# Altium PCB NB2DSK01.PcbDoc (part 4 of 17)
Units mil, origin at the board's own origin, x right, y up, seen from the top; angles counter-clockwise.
Board outline 11815 x 6500.03 mil, 8 copper layers (Top Layer, MidLayer1, MidLayer2, GND, PWR, MidLayer3, MidLayer4, Bottom Layer), stack 74.62 mil thick; 798 components, 1002 nets, 3927 pads, 3182 vias.
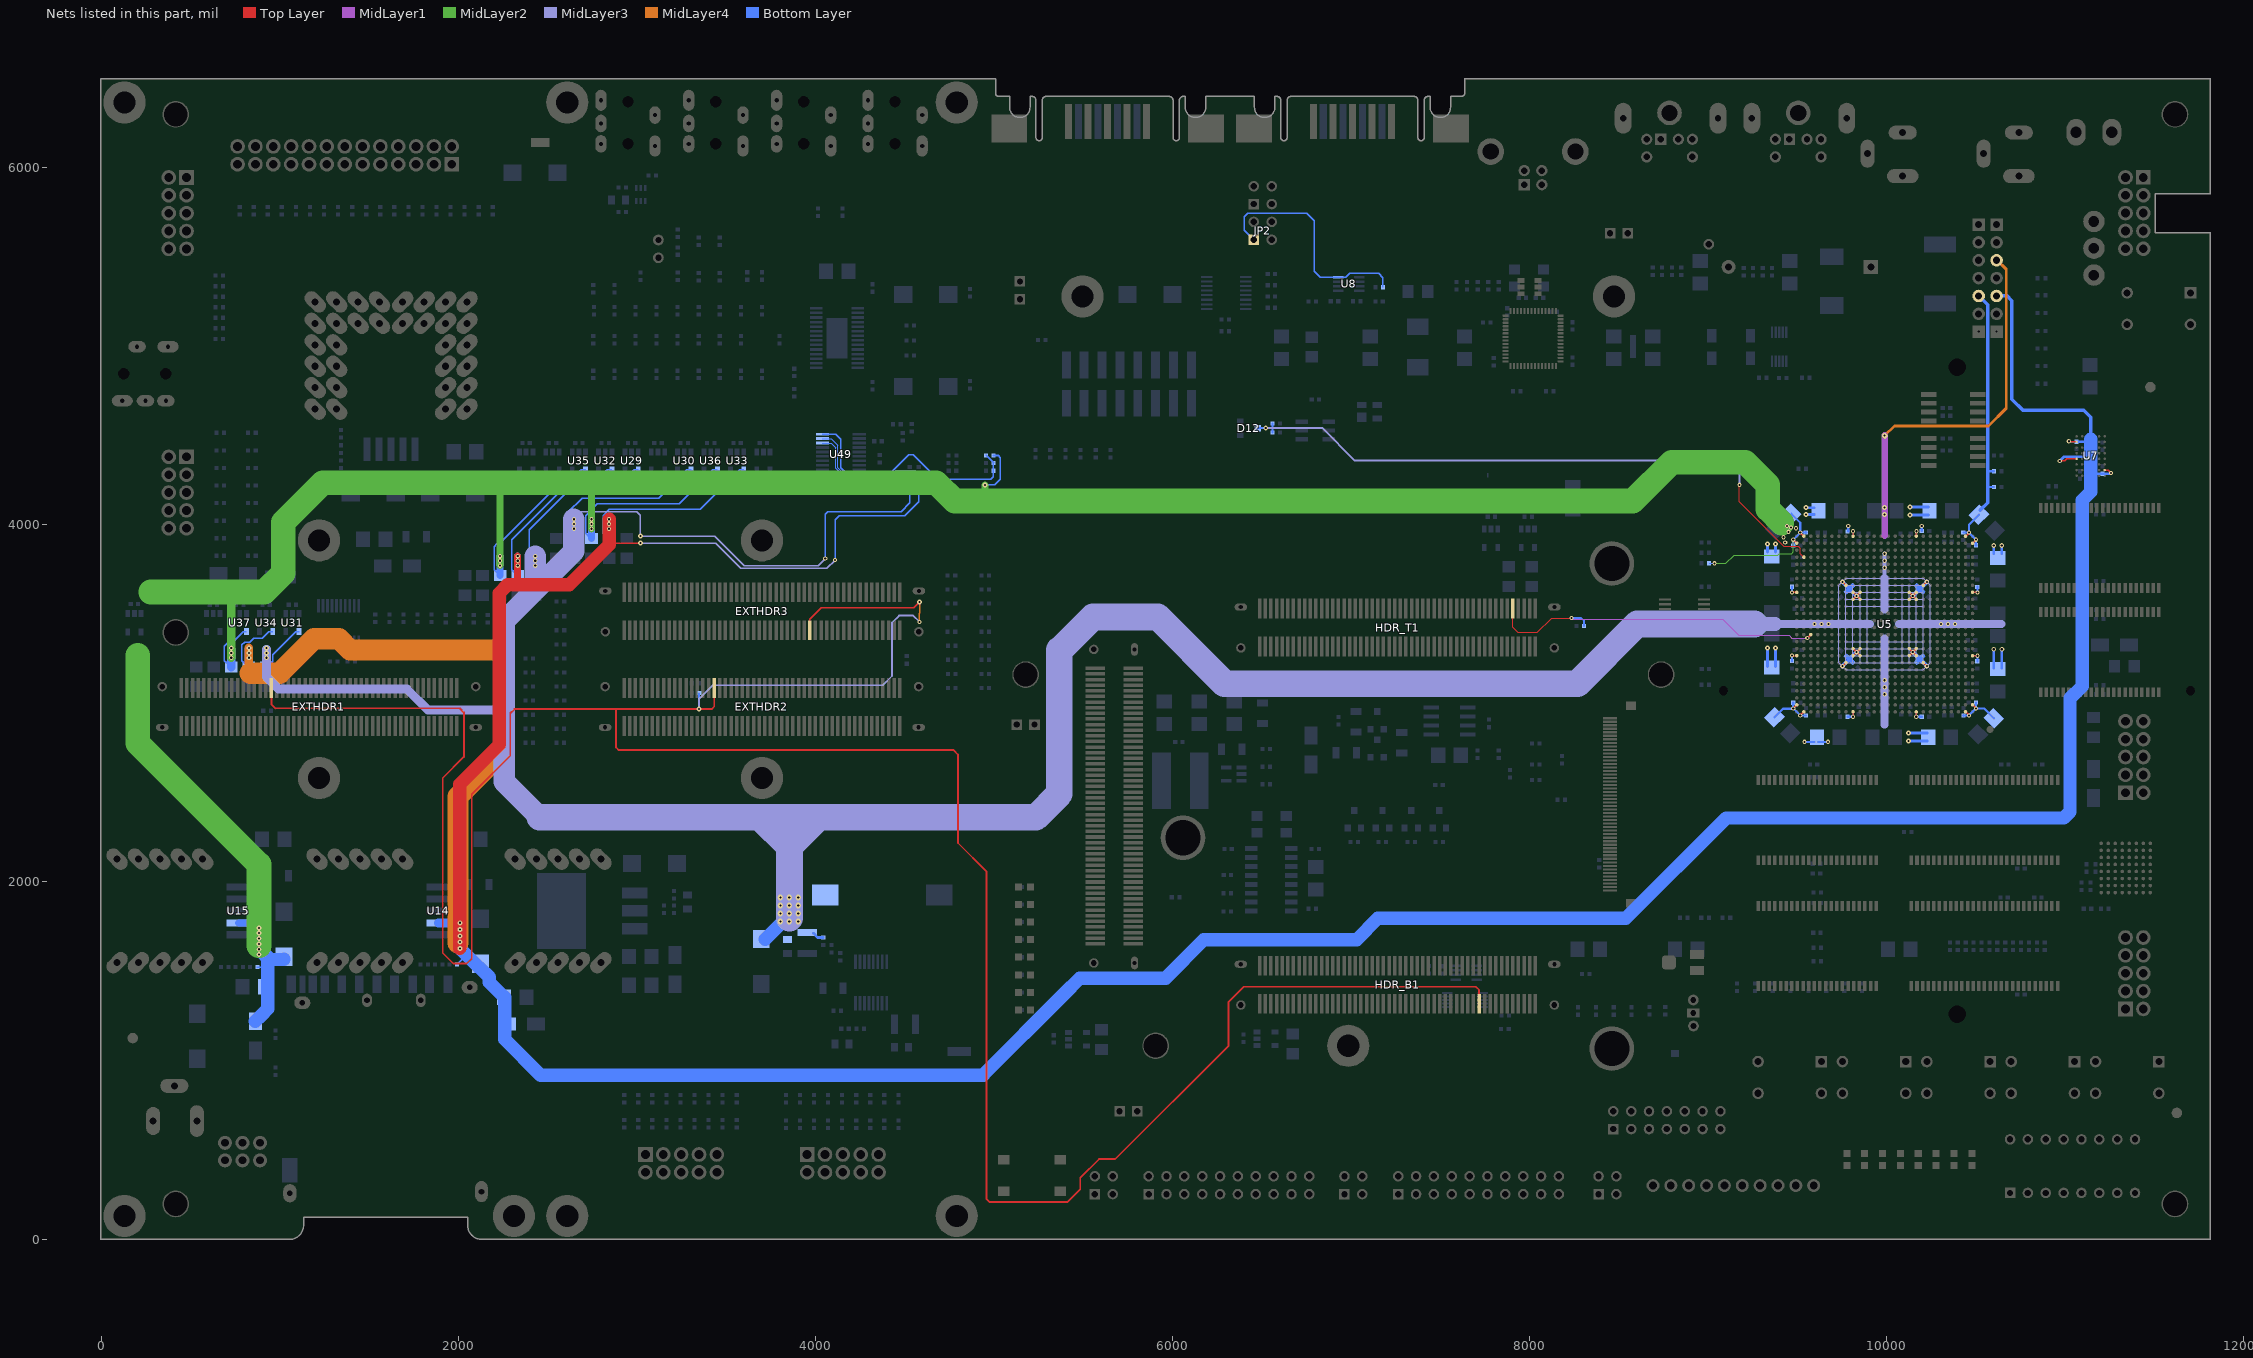
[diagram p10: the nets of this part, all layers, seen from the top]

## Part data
"Altium Logo BOT1" "Altium Logo Top1": library part D-000-0003, "Altium Logo for PCB"
BT1: library part D-302-0000, "Lithium Battery Holder for CR2032 3V Cell"
C1 C2 C3 C4 C137 C150 C160 C164 C168 C177 C180: library part D-101-0088, "Capacitor, Tantalum, 220uF 10% 10V MCCT-D (7343-31)"
C5 C6 C7 C8 C118: library part D-101-0078, "Capacitor, Ceramic, 100pF 5% 50V 0402 (1005) COG"
C9 C11 C14 C17 C26 C27 C28 C29 C38 C39 C40 C41 C42 C58 C59 C60 C61 C62 C63 C64 C65 C66 C67 C68 C69 C70 C71 C72 C73 C74 C75 C76 C77 C78 C79 C80 C81 C82 C83 C84 C115 C117 C119 C120 C121 C122 C125 C126 C127 C129 C134 C141 C153 C154 C155 C156 C174 C194 C195 C196 C198 C200 C202 C203 C204 C205 C206 C211 C212 C216 C219 C220 C221 C222 C227 C228 C229 C230 C235 C236 C237 C238 C239 C240 C241 C242 C243 C244 C245 C246 C247 C248 C249 C250 C251 C252 C253 C254 C255 C256 C257 C258 C259 C260 C261 C262 C263 C264 C265 C267 C268 C272: library part D-101-0080, "Capacitor, Ceramic, 0.1uF 10% 16V 0402 (1005) X7R"
C10 C15 C16 C18 C19 C20 C21 C22 C23 C24 C25 C34 C35 C36 C37 C54 C55 C56 C57 C114 C116 C123 C124 C132 C133 C135 C136 C140 C143 C158 C159 C162 C163 C166 C167 C169 C170 C193 C217 C218 C266 C273: library part D-101-0007, "Capacitor, Tantalum, 10uF 10% 20V MCCT-B (3528)"
C12 C13: library part D-101-0075, "Capacitor, Ceramic, 15pF 5% 50V 0402 (1005)"
C30 C31 C32 C33 C43 C44 C45 C46 C47 C48 C49 C50 C51 C52 C53 C85 C86 C87 C88 C89 C90 C91 C92 C93 C94 C95 C96 C97 C98 C99 C100 C101 C102 C103 C104 C105 C106 C107 C108 C109 C110 C111 C112 C113 C199 C201 C207 C208 C209 C210 C213 C214 C215 C223 C224 C225 C226 C231 C232 C233 C234: library part D-101-0077, "Capacitor, Ceramic, 10nF 10% 16V 0402 (1005) X7R"
C128 C130 C131 C139 C144 C151 C157 C161 C165: library part D-101-0027, "Capacitor, Ceramic, 1uF 10% 25V 1206 (3216) X7R"
C138 C142 C146 C148 C152 C197: library part D-101-0087, "Capacitor, Ceramic, 10uF 10% 10V 0805 (2012) X5R"
C145: library part D-101-0069, "Capacitor, Ceramic, 470pF 5% 50V 0402 (1005) COG"
C147 C149: library part D-101-0021, "Capacitor, Ceramic, 22uF -20%/+80% 10V 1210 (3225) Y5V"
C171 C173 C175 C176 C178 C179 C182 C183 C184 C185 C186 C187 C188 C190 C191 C192: library part D-101-0082, "Capacitor, Ceramic, 1uF 10% 6.3V 0402 (1005) X5R"
C172 C181 C189: library part D-101-0070, "Capacitor, Ceramic, 4.7nF 10% 25V 0402 (1005) X7R"
C269 C270: library part D-101-0059, "Capacitor, Ceramic, 22pF 5% 50V 0402 (1005) COG"
C271: library part D-101-0019, "Capacitor, Ceramic, 4.7nF 20% 250V Panasonic BC J Lead (CAPM7163) Y5V"
D1: library part D-150-0001, "Zener Diode, 5V 5W"
D2: library part D-150-0002, "Zener Diode, 7.5V 35mA"
D3: library part D-151-0001, "Schottky Diode, Dual-Serial, BAT54S 30V 200mA"
D4 D5 D6 D7 D8 D9 D10 D11: library part D-151-0000, "Schottky Diode, 3A 40V"
D12: library part D-150-0005, "Zener Diode, 3.3V"
DH1 DH2 HDR1 HDR2 HDR3: library part D-300-0014, "Header IDC, 2 x 5 Pin Right-Angle 2.54mm Pitch (Boxed-Male)"
EXTHDR1 EXTHDR2 EXTHDR3 HDR_B1 HDR_L1 HDR_T1: library part D-300-0026, "Connector, Molex Docking Station 100 Pin Female 53751"
F1: library part D-106-0002, "Mutifuse, SMD 8A"
F2 F3 F4 F5: library part D-106-0001, "Multifuse, SMD 1206, 350mA"
FD1 FD2 FD3: library part D-004-0001, "Fiducial - Round 1.5mm Top-Bottom"
FP1: library part "Generic No Pins"
GP1 GP2 GP3 GP4: library part D-300-0020, "Header IDC, 2 x 1 Pin Vertical 2.54mm Pitch (Non-Boxed, Male)"
HDR4: library part D-300-0022, "Header IDC, 2 x 5 Pin Right-Angle 2.54mm Pitch (Non-Boxed, Male)"
HDR5: library part D-300-0024, "Header IDC, 2 x 5 Pin Right-Angle 2.54mm Pitch (Non-Boxed, Male)"
HDR6: library part D-300-0015, "Header IDC, 2 x 13 Pin Right-Angle 2.54mm Pitch (Boxed-Male)"
HDR7: library part D-300-0017, "Header IDC, 2 x 7 Pin Vertical 2.54mm Pitch (Non-Boxed, Male)"
J1 J2 J3: library part D-300-0007, "Connector, 3 Conductor Power Jack 2 break 2 aux contacts"
J4: library part D-300-0000, "Connector, USB B Type, Right Angle, Thru Hole, White"
J5: library part D-300-0036, "MINI DIN R/A F/SHLD 6P GOLD PLATED--PURPLE PC99 RoHS Compliant"
J6: library part D-300-0037, "MINI-DIN R/A F/SHLD 6P GOLD PLATED--GREEN PC99 RoHS Compliant"
J7 J9: library part D-300-0060, "Connector DB9 SMD Male/Pins; SUYIN"
J8: library part D-300-0003, "Secure Digital Card Socket"
J10 J14: library part D-300-0033, "Connector, 3.5mm Stereo Audio Socket, Black, 2 break contacts (normals) and 2 auxiliary make contacts"
J11: library part D-300-0030, "Connector, 3.5mm Stereo Audio Socket, Red, 2 break contacts (normals) and 2 auxiliary make contacts"
J12: library part D-300-0031, "Connector, 3.5mm Stereo Audio Socket, Green, 2 break contacts (normals) and 2 auxiliary make contacts"
J13: library part D-300-0032, "Connector, 3.5mm Stereo Audio Socket, Blue, 2 break contacts (normals) and 2 auxiliary make contacts"
J15: library part D-300-0061, "Header, 2x8, 0.1\", Straight, SMT"
JP1 JP2 JP3 JP4 JP5: library part D-300-0019, "Header IDC, 2 x 2 Pin Vertical 2.54mm Pitch (Non-Boxed, Male)"
L1: library part D-102-0001, "Inductor, Magnetic Core 10uH 2.3A 70mR INDP7575"
L2: library part D-102-0000, "Inductor, 2.2uH 9A 6.8mR 20% INDP182140 SB18062R2MSB"
LCD1: library part D-300-0010, "Connector, 1 x 50 Pin, 0.5mm Pitch for Hitachi TX09D50VM1CAA TFT"
LED1 LED2 LED3 LED4 LED5 LED6 LED7 LED8: library part D-153-0009, "LED, Red 0603 (1608) 63mCd"
LED9 LED10 LED11 LED12 LED13 LED14 LED15 LED16: library part D-153-0002
LOGO1 LOGO2: library part D-000-0000
MH1 MH2 MH3 MH4 MH5 MH6 MH7 MH8: library part D-001-0001, "Mounting Hole, M3 Screw, Plated, Square Pad"
NT1 NT5: library part D-002-0003, "Net-Tie, Surface Mount, 2 x 1.6mm x 0.8mm SMT Pads - For 0.8mm Track"
NT2: library part D-002-0006, "Net-Tie, Surface Mount, 2 x 0.8mm x 0.4mm SMT Pads - For 0.4mm Track"
NT3 NT6: library part D-002-0002, "Net-Tie, Surface Mount, 2 x 0.4mm x 0.2mm SMT Pads - For 0.2mm Track"
NT4: library part D-002-0004, "Net-Tie, Surface Mount, 2 x 2.0mm x 0.8mm SMT Pads - For 0.8mm Track"
PB_MH1 PB_MH2 PB_MH3 PB_MH4 PB_MH5 PB_MH6 PB_MH7 PB_MH8 PB_MH9 PB_MH10 PB_MH11 PB_MH12 PB_MH13 PB_MH14: library part D-001-0006, "Mounting Hole for Solder Standoff, M3 Screw, Plated, Round Pad"
Q1 Q2 Q3 Q4: library part D-152-0001, "Transistor, FMMT491A Small Signal NPN"
R1 R6 R7 R11 R12 R13 R14 R19 R52 R56 R82 R83 R84 R85 R88 R89 R145 R146 R147 R148 R149 R150 R151 R152 R153 R154 R155 R156 R157 R158 R159 R190 R191 R192 R193 R198 R199 R200 R201 R206 R208 R209 R210 R211 R216 R217 R218 R219 R224 R226 R227 R228 R229 R234 R235 R236 R237 R242 R244 R245 R246 R247 R252 R253 R254 R255 R260 R262 R263 R264 R265 R270 R271 R272 R273 R278 R280 R281 R282 R283 R288 R289 R290 R291 R297 R298 R299 R300 R304 R314 R316 R318 R319: library part D-100-0088, "Resistor, 4K7 1% 0402 (1005)"
R2 R50 R51 R315: library part D-100-0108, "Resistor, 27R 1% 0402 (1005)"
R3 R4 R10 R17 R62: library part D-100-0085, "Resistor, 5R6 1% 0402 (1005)"
R5 R34 R39 R43 R48 R49 R77 R122 R123 R127 R130 R161 R296 R302 R303 R309: library part D-100-0121, "Resistor, 1K 1% 0402 (1005)"
R8 R9 R15 R16 R25 R26 R27 R28 R29 R30 R31 R32 R33 R35 R37 R38 R71 R72 R86 R87 R90 R91 R194 R195 R196 R197 R202 R203 R204 R205 R207 R212 R213 R214 R215 R220 R221 R222 R223 R225 R230 R231 R232 R233 R238 R239 R240 R241 R243 R248 R249 R250 R251 R256 R257 R258 R259 R261 R266 R267 R268 R269 R274 R275 R276 R277 R279 R284 R285 R286 R287 R292 R293 R294 R295 R301 R305 R306 R307 R308: library part D-100-0131, "Resistor, 100R 1% 0402 (1005)"
R18 R20 R131 R132 R136 R142 R143 R144: library part D-100-0107, "Resistor, 2K2 1% 0402 (1005)"
R21 R22 R23 R24 R36 R61: library part D-100-0090, "Resistor, 47R 1% 0402 (1005)"
R40 R42 R47 R109 R112 R113 R114 R115 R121 R124 R125 R126 R129 R133 R134: library part D-100-0092, "Resistor, 47K 1% 0402 (1005)"
R41: library part D-100-0097, "Resistor, 3K9 1% 0402 (1005)"
R44 R312: library part D-100-0086, "Resistor, 5K6 1% 0402 (1005)"
R45 R46 R55 R81: library part D-100-0125, "Resistor, 15K 1% 0402 (1005)"
R53 R92 R93 R94 R95 R96 R97 R98 R99 R100 R101 R102 R103 R104 R105 R106 R107: library part D-100-0111, "Resistor, 270R 1% 0402 (1005)"
R54 R60 R138 R139 R140 R141 R189 R320: library part D-100-0126, "Resistor, 120R 1% 0402 (1005)"
R57 R135: library part D-100-0115, "Resistor, 220R 1% 0402 (1005)"
R58 R59 R67 R70 R184 R185 R187 R311: library part D-100-0105, "Resistor, 2K7 1% 0402 (1005)"
R63 R69 R110 R111 R118 R119: library part D-100-0132, "Resistor, 100K 1% 0402 (1005)"
R64: library part D-100-0074, "Resistor, 8K2 1% 0402 (1005)"
R65: library part D-100-0084, "Resistor, 680K 1% 0402 (1005)"
R66: library part D-100-0102, "Resistor, 33R 1% 0402 (1005)"
R68: library part D-100-0109, "Resistor, 27K 1% 0402 (1005)"
R73 R137 R160 R181 R182 R183 R186 R188 R313: library part D-100-0130, "Resistor, 10K 1% 0402 (1005)"
R74: library part D-100-0104, "Resistor, 330R 1% 0402 (1005)"
R75 R76 R78 R79 R117: library part D-100-0114, "Resistor, 22K 1% 0402 (1005)"
R80 R108 R128: library part D-100-0098, "Resistor, 3K3 1% 0402 (1005)"
R116 R120: library part D-100-0081, "Resistor, 68K 1% 0402 (1005)"
R162 R163 R164 R165 R166 R167 R168 R169 R170 R171 R172 R173 R174 R175 R176 R177 R178 R179 R180: library part D-100-0007, "Resistor, 0R047, LRC02P, SMD, 1206, Thick Film, Current Sense, 1%"
R317: library part D-100-0059, "Resistor, 10M 1%1206 (3216)"
SW1 SW2 SW3 SW4 SW5 SW9: library part D-301-0002, "Switch, DPNO Push Button Through-Hole"
SW6: library part D-301-0000, "Switch, SPDT Subminiature Toggle"
SW7: library part D-301-0003, "Switch, DIP Black 8-Way 300mil x 100mil"
SW8: library part D-301-0001, "Switch, SPNO Push Button SMD"
TP1 TP2 TP3 TP4 TP5 TP6 TP7 TP8 TP9 TP10 TP11 TP12 TP13 TP14 TP15: library part D-006-0000, "Test Point, PCB Mount with Silkscreen Box"
TS1: library part D-300-0001, "Connector, Screw Terminal Block, Green, 10-Way, 2.54mm"
U1: library part D-220-0000, "MAX1037EKA-T, 2.7V to 5.5V, Low-Power, 4-Channel, I2C, 8-Bit ADCs"
U2: library part D-206-0001, "DS1391U-33, SPI Real-Time Clock with Trickle Charger, 3.3V, 10-Pin uMax/uSOP"
U3: library part D-206-0000, "ICS307-02, SPI Programmable Clock Generator"
U4: library part D-222-0001, "MAX5841MEUB, Quad, 10-Bit, Low-Power, I2C, DAC"
U5: library part D-241-0001, "FPGA, Xilinx Spartan3-1500 FG676 Speed=4"
U6: library part D-202-0001, "AD7843ARU,12-bit SPI Touch Screen Digitizer"
U7: library part D-262-0000, "XCF00P Series, Platform Flash In-System Programmable Configuration 1.8V PROM, 48 Ball BGA, 8-Megabit, Commercial Grade"
U8: library part D-221-0007, "MAX3051EKA-T High-Speed CAN Transceiver SOT23-8"
U9: library part D-204-0000, "LM317LDR2, 3-Terminal Adjustable Regulator"
U10: library part D-204-0004, "LM1084IS-ADJ, 5A Low Dropout Positive Regulators"
U11: library part D-204-0003, "LM2704MF, Micropower Step-up DC/DC Converter, 550mA Peak Current Limit, 2.2-7V Input, 20V Max Output"
U12: library part D-204-0002, "MAX1831EEE, 3A, 1MHz, Low-Voltage, Step-Down Regulators with Synchronous Rectification and Internal Switches"
U13: library part D-221-0002, "MAX3232EUE, 3.0V to 5.5V, Low-Power, up to 1Mbps, True RS-232 Transceivers Using Four 0.1µF External Capacitors"
U14 U15 U16: library part D-204-0014, "TPS75501KTTT, 5A, Low Dropout, Adjustable, Linear Voltage Regulator, TO-263"
U17: library part D-201-0002, "LM4849MH Stereo 2W Audio Power Amplifier with DC Volume Control and Input Mux"
U18: library part D-201-0004, "MAX9812L, Microphone Pre-Amplifier, single, 20dB gain, Shutdown"
U19: library part D-263-0002, "Dual Addressable Switch Plus 1KB Memory"
U20 U21: library part D-262-0006
U22 U23 U27 U28: library part D-260-0000, "K6R4016V1D-TC10T, 256K x 16-Bit SRAM, TSOP44"
U24: library part D-262-0001, "S29GL256N11FFIV10, 256 Megabit (16M x 16) 3.0V Page Mode Flash Memory"
U25 U26: library part D-261-0000, "MT48LC16M16A2TG, 256 Mbit High-Speed CMOS SDRAM, 16Mb x 16Bit x 4 Banks, TSOP54"
U29 U30 U31 U32 U33 U34 U35 U36 U37 U38 U39 U40 U41 U42 U43 U44 U45 U46 U47: library part D-204-0012, "MAX4372 High Side Current Sense Amplifier"
U48 U49: library part D-220-0003, "MAX1229, 12bit ADC, 12 channel, 3.3V, SPI"
U50: library part D-243-0000, "MAX6315, Open-Drain Output SOT Reset IC, Customized Reset Thresholds, Timeout Delays"
U51: library part D-204-0001, "NUP2201MR6, Low Capacitance Diode Array, USB Protection"
U52: library part D-221-0004, "CY7C68001-56LFC, EZ-USB SX2 High-Speed USB Interface"
UH1 UH2: library part D-300-0021, "Header IDC, 2 x 10 Pin Vertical 2.54mm Pitch (Non-Boxed, Male)"
VR1: library part D-105-0000, "Potentiometer, 20K 4mm Cermet PCB SMT Trimmer"
VR2: library part D-105-0001, "Potentiometer, 2 x 5K Linear 9mm PCB Mount Fluted Shaft"
Y1: library part D-103-0002, "Crystal, 32.768 KHz Surface Mount"
Y2: library part D-103-0012, "Crystal, SMD, 20.000000MHz Stab=30ppm 20.0pF"
Y3: library part D-103-0013, "Crystal, SMD, 24.000000MHz Stab=30ppm 20.0pF"

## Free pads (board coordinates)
  oval 137.8x78.74 hole 39.37 slot 98.43 at 45 deg rot 45 paste+0 mask+0: 0(88.68,1548.45) 0(208.68,1548.45) 0(328.68,1548.45) 0(448.68,1548.45) 0(568.68,1548.45) 0(1208.68,1548.45) 0(1328.68,1548.45) 0(1448.68,1548.45) 0(1568.68,1548.45) 0(1688.68,1548.45) 0(1688.68,5128.45) 0(1688.68,5248.45) 0(1808.68,5128.45) 0(1808.68,5248.45) 0(1928.68,4648.45) 0(1928.68,4768.45) 0(1928.68,4888.45) 0(1928.68,5008.45) 0(1928.68,5128.45) 0(1928.68,5248.45) 0(2048.68,4648.45) 0(2048.68,4768.45) 0(2048.68,4888.45) 0(2048.68,5008.45) 0(2048.68,5128.45) 0(2048.68,5248.45) 0(2318.68,1548.45) 0(2438.68,1548.45) 0(2558.68,1548.45) 0(2678.68,1548.45) 0(2798.68,1548.45)
  oval 137.8x78.74 hole 39.37 slot 98.43 at 135 deg rot 135 paste+0 mask+0: 0(88.68,2128.45) 0(208.68,2128.45) 0(328.68,2128.45) 0(448.68,2128.45) 0(568.68,2128.45) 0(1198.68,4648.45) 0(1198.68,4768.45) 0(1198.68,4888.45) 0(1198.68,5008.45) 0(1198.68,5128.45) 0(1198.68,5248.45) 0(1208.68,2128.45) 0(1318.68,4648.45) 0(1318.68,4768.45) 0(1318.68,4888.45) 0(1318.68,5008.45) 0(1318.68,5128.45) 0(1318.68,5248.45) 0(1328.68,2128.45) 0(1438.68,5128.45) 0(1438.68,5248.45) 0(1448.68,2128.45) 0(1558.68,5128.45) 0(1558.68,5248.45) 0(1568.68,2128.45) 0(1688.68,2128.45) 0(2318.68,2128.45) 0(2438.68,2128.45) 0(2558.68,2128.45) 0(2678.68,2128.45) 0(2798.68,2128.45)
  rect 118.11x225 smd far side: 0(4120.08,5045.28)
  rect 70x50 hole 31.5: 0(8916.89,1266.02)
  rect 70x70 hole 11.81 mask+0: 0(10514.96,5081.98) 0(10614.96,5081.98)
  rect 70x70 hole 39.37: 0(10514.96,5681.95) 0(10614.96,5681.95)
  round 157.48 on Plane1: 2(177.17,1125.98) 2(11579.68,5072.45) 2(11624.68,706.45)
  round 157.48 on Plane2: 2(177.17,1125.98) 2(11579.68,5072.45) 2(11624.68,706.45)

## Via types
v1: diameter 23.62, hole 11.81, Top Layer to Bottom Layer, tented both sides, 1950 vias
v2: diameter 27.56, hole 11.81, Top Layer to Bottom Layer, tented both sides, 679 vias
v3: diameter 23.62, hole 11.81, Top Layer to Bottom Layer, 194 vias
v4: diameter 31.5, hole 11.81, Top Layer to Bottom Layer, tented both sides, 178 vias
v5: diameter 21.65, hole 11.81, Top Layer to Bottom Layer, tented both sides, 67 vias
v6: diameter 23.62, hole 11.81, Top Layer to Bottom Layer, tented bottom, 53 vias
v7: diameter 26, hole 11.81, Top Layer to Bottom Layer, tented both sides, 21 vias
v8: diameter 26, hole 11.81, Top Layer to Bottom Layer, 13 vias
v9: diameter 28, hole 11.81, Top Layer to Bottom Layer, 8 vias
v10: diameter 25.59, hole 11.81, Top Layer to Bottom Layer, tented both sides, 7 vias
v11: diameter 39.37, hole 11.81, Top Layer to Bottom Layer, tented both sides, 5 vias
v12: diameter 30, hole 11.81, Top Layer to Bottom Layer, 3 vias
v13: diameter 30, hole 11.81, Top Layer to Bottom Layer, tented both sides, 2 vias
v14: diameter 23, hole 11.81, Top Layer to Bottom Layer, tented both sides, 1 vias
v15: diameter 26.56, hole 11.81, Top Layer to Bottom Layer, tented both sides, 1 vias

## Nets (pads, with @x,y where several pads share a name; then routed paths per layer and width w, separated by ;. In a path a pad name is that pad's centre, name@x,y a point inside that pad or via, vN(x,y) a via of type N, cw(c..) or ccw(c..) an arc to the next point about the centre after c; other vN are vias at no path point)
1MBPS_EN: JP2.1 R55.2 U8.8 | length 1322.3
  Bottom Layer w7.87: JP2.1@6455.12,5596.85 6401,5650.97 6401,5726 6420,5745 6751,5745 6793.84,5702.16 6793.84,5421.16 6827.13,5387.87 U8.8@6927,5387.87 6971.2,5387.87 6992.47,5409.13 7153.87,5409.13 7178.65,5384.35 R55.2@7178.65,5330.7
1V2: C18.1 C19.1 C20.1 C21.1 C22.1 C23.1 C24.1 C25.1 C26.1 C27.1 C28.1 C29.1 C30.1 C31.1 C32.1 C33.1 C148.2 C149.2 C150.1 L2.2 R67.2 R162.1 R163.1 R164.1 R184.2 TP9.1 U5.H8 U5.H19 U5.J9 U5.J10 U5.J17 U5.J18 U5.K9 U5.K10 U5.K17 U5.K18 U5.U9 U5.U10 U5.U17 U5.U18 U5.V9 U5.V10 U5.V17 U5.V18 U5.W8 U5.W19 U29.4 U30.4 U31.4 | length 33374.5
  Top Layer w7.87: v10(9751.97,3208.66) U5.W8@9771.65,3228.35 ; v10(9751.97,3681.1) U5.H8@9771.65,3661.42 ; U5.V9@9811.02,3267.72 v10(9830.71,3287.4) ; U5.U9@9811.02,3307.09 v10(9830.71,3287.4) ; U5.K9@9811.02,3582.68 v10(9830.71,3602.36) ; U5.J9@9811.02,3622.05 v10(9830.71,3602.36) ; U5.V10@9850.39,3267.72 v10(9830.71,3287.4) ; U5.U10@9850.39,3307.09 v10(9830.71,3287.4) ; U5.K10@9850.39,3582.68 v10(9830.71,3602.36) ; U5.J10@9850.39,3622.05 v10(9830.71,3602.36) ; U5.V17@10125.98,3267.72 v10(10145.67,3287.4) ; U5.U17@10125.98,3307.09 v10(10145.67,3287.4) ; U5.K17@10125.98,3582.68 v10(10145.67,3602.36) ; U5.J17@10125.98,3622.05 v10(10145.67,3602.36) ; U5.V18@10165.35,3267.72 v10(10145.67,3287.4) ; U5.U18@10165.35,3307.09 v10(10145.67,3287.4) ; U5.K18@10165.35,3582.68 v10(10145.67,3602.36) ; U5.J18@10165.35,3622.05 v10(10145.67,3602.36) ; U5.W19@10204.72,3228.35 v1(10224.41,3208.66) ; U5.H19@10204.72,3661.42 v10(10224.41,3681.1)
  MidLayer1 w38: 9988.19,3940.95 v2(9988.19,4059.06) v2(9988.19,4098.43) v4(9988.19,4500)
  MidLayer4 w15.75: v4(9988.19,4500) 10042.64,4554.45 10570.2,4554.45 10669.29,4653.54 10669.29,5431.62 10616.94,5483.97 TP9.1@10614.94,5485.97
  MidLayer3 w5: 9732.07,3438.69 9732.07,3228.56 v10(9751.97,3208.66) ; 9732.07,3451.07 9732.07,3661.21 v10(9751.97,3681.1) ; 9771.44,3228.56 9771.44,3438.69 ; 9771.44,3451.07 9771.44,3661.21 ; 9771.87,3267.93 9810.81,3267.93 ; 9771.87,3307.3 9810.81,3307.3 ; 9771.87,3346.67 9810.81,3346.67 ; 9771.87,3543.1 9810.81,3543.1 ; 9771.87,3582.47 9810.81,3582.47 ; 9771.87,3621.84 9810.81,3621.84 ; 9810.81,3438.69 9810.81,3346.67 ; 9810.81,3451.07 9810.81,3543.1 ; 9850.18,3438.69 9850.18,3346.67 ; 9850.18,3451.07 9850.18,3543.1 ; 9889.55,3438.69 9889.55,3346.67 ; 9889.55,3451.07 9889.55,3543.1 ; 9982,3188.76 9771.87,3188.76 v10(9751.97,3208.66) ; 9982,3228.56 9889.55,3228.56 ; 9982,3267.93 9889.55,3267.93 ; 9982,3307.3 9889.55,3307.3 ; 9982,3346.67 9889.55,3346.67 ; 9982,3543.1 9889.55,3543.1 ; 9982,3582.47 9889.55,3582.47 ; 9982,3621.84 9889.55,3621.84 ; 9982,3661.21 9889.55,3661.21 ; 9982,3701 9771.87,3701 v10(9751.97,3681.1) ; 9994.38,3188.76 10204.51,3188.76 v1(10224.41,3208.66) ; 9994.38,3228.56 10086.83,3228.56 ; 9994.38,3267.93 10086.83,3267.93 ; 9994.38,3307.3 10086.83,3307.3 ; 9994.38,3346.67 10086.83,3346.67 ; 9994.38,3543.1 10086.83,3543.1 ; 9994.38,3582.47 10086.83,3582.47 ; 9994.38,3621.84 10086.83,3621.84 ; 9994.38,3661.21 10086.83,3661.21 ; 9994.38,3701 10204.51,3701 v10(10224.41,3681.1) ; 10086.83,3438.69 10086.83,3346.67 ; 10086.83,3451.07 10086.83,3543.1 ; 10126.2,3438.69 10126.2,3346.67 ; 10126.2,3451.07 10126.2,3543.1 ; 10165.57,3438.69 10165.57,3346.67 ; 10165.57,3451.07 10165.57,3543.1 ; 10204.51,3267.93 10165.57,3267.93 ; 10204.51,3307.3 10165.57,3307.3 ; 10204.51,3346.67 10165.57,3346.67 ; 10204.51,3543.1 10165.57,3543.1 ; 10204.51,3582.47 10165.57,3582.47 ; 10204.51,3621.84 10165.57,3621.84 ; 10204.94,3228.56 10204.94,3438.69 ; 10204.94,3451.07 10204.94,3661.21 ; 10244.31,3438.69 10244.31,3228.56 v1(10224.41,3208.66) ; 10244.31,3451.07 10244.31,3661.21 v10(10224.41,3681.1) ; v10(9751.97,3208.66) 9771.87,3228.56 9810.81,3228.56 ; v10(9751.97,3681.1) 9771.87,3661.21 9810.81,3661.21 ; 9810.81,3228.56 9850.18,3228.56 ; 9810.81,3228.56 9810.81,3267.93 ; 9810.81,3267.93 9850.18,3267.93 ; 9810.81,3267.93 9810.81,3307.3 ; 9810.81,3307.3 9810.81,3346.67 ; 9810.81,3307.3 9850.18,3307.3 ; 9810.81,3346.67 9850.18,3346.67 ; 9810.81,3543.1 9850.18,3543.1 ; 9810.81,3543.1 9810.81,3582.47 ; 9810.81,3582.47 9850.18,3582.47 ; 9810.81,3582.47 9810.81,3621.84 ; 9810.81,3621.84 9850.18,3621.84 ; 9810.81,3621.84 9810.81,3661.21 ; 9810.81,3661.21 9850.18,3661.21 ; 9850.18,3228.56 9889.55,3228.56 ; 9850.18,3228.56 9850.18,3267.93 ; 9850.18,3267.93 9889.55,3267.93 ; 9850.18,3267.93 9850.18,3307.3 ; 9850.18,3307.3 9889.55,3307.3 ; 9850.18,3307.3 9850.18,3346.67 ; 9850.18,3346.67 9889.55,3346.67 ; 9850.18,3543.1 9850.18,3582.47 ; 9850.18,3543.1 9889.55,3543.1 ; 9850.18,3582.47 9850.18,3621.84 ; 9850.18,3582.47 9889.55,3582.47 ; 9850.18,3621.84 9850.18,3661.21 ; 9850.18,3621.84 9889.55,3621.84 ; 9850.18,3661.21 9889.55,3661.21 ; 9889.55,3228.56 9889.55,3267.93 ; 9889.55,3267.93 9889.55,3307.3 ; 9889.55,3307.3 9889.55,3346.67 ; 9889.55,3543.1 9889.55,3582.47 ; 9889.55,3582.47 9889.55,3621.84 ; 9889.55,3621.84 9889.55,3661.21 ; 10086.83,3228.56 10086.83,3267.93 ; 10086.83,3228.56 10126.2,3228.56 ; 10086.83,3267.93 10086.83,3307.3 ; 10086.83,3267.93 10126.2,3267.93 ; 10086.83,3307.3 10086.83,3346.67 ; 10086.83,3307.3 10126.2,3307.3 ; 10086.83,3346.67 10126.2,3346.67 ; 10086.83,3543.1 10086.83,3582.47 ; 10086.83,3543.1 10126.2,3543.1 ; 10086.83,3582.47 10086.83,3621.84 ; 10086.83,3582.47 10126.2,3582.47 ; 10086.83,3621.84 10086.83,3661.21 ; 10086.83,3621.84 10126.2,3621.84 ; 10086.83,3661.21 10126.2,3661.21 ; 10126.2,3228.56 10126.2,3267.93 ; 10126.2,3228.56 10165.57,3228.56 ; 10126.2,3267.93 10126.2,3307.3 ; 10126.2,3267.93 10165.57,3267.93 ; 10126.2,3307.3 10126.2,3346.67 ; 10126.2,3307.3 10165.57,3307.3 ; 10126.2,3346.67 10165.57,3346.67 ; 10126.2,3543.1 10126.2,3582.47 ; 10126.2,3543.1 10165.57,3543.1 ; 10126.2,3582.47 10126.2,3621.84 ; 10126.2,3582.47 10165.57,3582.47 ; 10126.2,3621.84 10126.2,3661.21 ; 10126.2,3621.84 10165.57,3621.84 ; 10126.2,3661.21 10165.57,3661.21 ; 10165.57,3228.56 10204.51,3228.56 v1(10224.41,3208.66) ; 10165.57,3228.56 10165.57,3267.93 ; 10165.57,3267.93 10165.57,3307.3 ; 10165.57,3307.3 10165.57,3346.67 ; 10165.57,3543.1 10165.57,3582.47 ; 10165.57,3582.47 10165.57,3621.84 ; 10165.57,3621.84 10165.57,3661.21 ; 10165.57,3661.21 10204.51,3661.21 v10(10224.41,3681.1)
  MidLayer3 w7.87: v1(2647.64,4031.5) 2690.94,4074.8 3000,4074.8 3019.69,4055.12 v2(3019.69,3937.01) 3437.01,3937.01 3602.36,3771.65 4015.75,3771.65 v1(4055.12,3811.02)
  MidLayer3 w22: 9988.19,3701.96 v1(9988.19,3759.84) v1(9988.19,3799.21) v1(9988.19,3838.58)
  MidLayer3 w44: 9988,2881 9988.07,3051.18 9988.08,3090.55 v1(9988.19,3129.92) 9988.19,3363.94
  MidLayer3 w45: 9338.58,3444.88 v1(9594.49,3444.88) v1(9633.86,3444.88) v1(9673.23,3444.88) 9907.11,3444.88 ; 9988.19,3526.96 9988.19,3701.96 ; 10068.11,3444.88 v1(10303.15,3444.88) v1(10342.52,3444.88) v1(10381.89,3444.88) 10641.73,3444.88
  MidLayer3 w50: v2@925.2,3303.15 v2(925.2,3283.46) v2(925.2,3255.91) 925.2,3149.61 994.09,3080.71 1712.6,3080.71 1830.71,2962.6 2230.32,2962.6
  MidLayer3 w78.74: 9157.48,3444.88 9374.02,3444.88
  MidLayer3 w120: 2431.1,3663.69 v1(2431.1,3771.65) v1(2431.1,3799.21) v1(2431.1,3824.8) ; 2456.69,2362.21 2257,2561.9 2257,3461.72 2647.64,3852.36 v1(2647.64,3978.35) v1(2647.64,4005.91) v1(2647.64,4031.5)
  MidLayer3 w149.61: 2456.69,2362.21 3690.97,2362.21 ; 3854.72,1798.45 3854.72,1823.45 3854.72,1868.45 3854.72,1913.45 3854.72,2198.45 ; 5366.14,3299.21 5366.14,2909.45 5366.14,2494.14 5234.21,2362.21 4818.9,2362.21 4018.48,2362.21 ; 5370.08,3299.21 5555.12,3484.25 5917.32,3484.25 6291.34,3110.24 8267.72,3110.24 8602.36,3444.88 9259.84,3444.88 ; 3690.97,2362.21 3854.72,2198.45 ; 3690.97,2362.21 3854.72,2362.21 ; 3854.72,2198.45 3854.72,2362.21 ; 3854.72,2198.45 4018.48,2362.21 ; 3854.72,2362.21 4018.48,2362.21
  Bottom Layer w7.87: R164.1@925.2,3200.79 927.17,3202.76 960.63,3236.22 960.63,3271.65 1090.91,3401.94 U31.4@1108.46,3401.94 ; R162.1@2429.13,3716.54 2397.64,3748.03 2397.64,3972.44 2637.8,4212.6 2889.76,4212.6 2984.61,4307.45 U29.4@3008.07,4307.45 ; R163.1@2641.73,3925.2 2614.17,3952.76 2614.17,4070.87 2692.91,4149.61 3122.05,4149.61 3279.89,4307.45 U30.4@3303.35,4307.45 ; v1(4055.12,3811.02) 4055.12,4060.12 4069.8,4074.8 4480.31,4074.8 4528.77,4123.26 R184.2@4528.77,4186.13
  Bottom Layer w12: v1(9539.88,2785) C24.1@9595,2785 ; C24.1@9615,2785 v1(9670.12,2785)
  Bottom Layer w15: C149.2@3988.68,1713.45 4012.5,1689.63 R67.2@4043.68,1689.63
  Bottom Layer w15.75: C23.1@9332.73,3206.56 v2(9332.73,3311.56) ; C25.1@9332.73,3847.49 v2(9332.73,3892.49) ; C23.1@9377.73,3206.56 v2(9377.73,3311.56) ; C25.1@9377.73,3847.49 v2(9377.73,3892.49) ; v2(9548.46,4096.32) C21.1@9593.46,4096.32 ; v2(9548.51,4057.41) C21.1@9593.51,4057.41 ; v2(10121.57,2789.42) C22.1@10226.57,2789.42 ; v2(10121.57,2834.42) C22.1@10226.57,2834.42 ; v2(10129.45,4055.87) C20.1@10234.45,4055.87 ; v2(10129.45,4100.87) C20.1@10234.45,4100.87 ; C18.1@10599.17,3839.63 v2(10599.17,3884.63) ; C19.1@10599.19,3198.69 v2(10599.19,3303.69) ; C18.1@10644.17,3839.63 v2(10644.17,3884.63) ; C19.1@10644.19,3198.69 v2(10644.19,3303.69)
  Bottom Layer w23.62: v10(9751.97,3208.66) 9791.34,3248.03 ; v10(9751.97,3681.1) 9791.34,3641.73 ; C32.1@9774.46,3264.91 9791.34,3248.03 ; C29.1@9774.46,3624.85 9791.34,3641.73 ; C27.1@9808.22,3231.15 9791.34,3248.03 ; C31.1@9808.22,3658.61 9791.34,3641.73 ; v10(9830.71,3287.4) 9791.34,3248.03 ; v10(9830.71,3602.36) 9791.34,3641.73 ; v10(10145.67,3287.4) 10185.04,3248.03 ; v10(10145.67,3602.36) 10185.04,3641.73 ; C30.1@10168.16,3231.15 10185.04,3248.03 ; C33.1@10168.16,3658.61 10185.04,3641.73 ; C26.1@10201.92,3264.91 10185.04,3248.03 ; C28.1@10201.92,3624.85 10185.04,3641.73 ; v1(10224.41,3208.66) 10185.04,3248.03 ; v10(10224.41,3681.1) 10185.04,3641.73
  Bottom Layer w39.37: R162.1@2431.1,3716.54 v1(2431.1,3771.65) v1(2431.1,3799.21) v1(2431.1,3824.8) ; R163.1@2647.64,3923.23 v1(2647.64,3978.35) v1(2647.64,4005.91) v1(2647.64,4031.5)
  Bottom Layer w50: R164.1@925.2,3204.72 v2(925.2,3255.91) v2(925.2,3283.46) v2@925.2,3303.15
  Bottom Layer w75: C150.1@3719.39,1679.5 3811.01,1771.12 3833.34,1793.45
  other v1: 9988.19,3051.18 9988.19,3090.55 9830.71,3602.36
  other v2: 925.2,3311.02
  other v4: 3803.68,1778.45 3853.68,1778.45 3903.68,1778.45 3803.68,1823.45 3853.68,1823.45 3903.68,1823.45 3803.68,1868.45 3853.68,1868.45 3903.68,1868.45 3803.68,1913.45 3853.68,1913.45 3903.68,1913.45
1V2D: C261.2 R184.1 U49.8 | length 716.8
  Bottom Layer w5: U49.8@4039.37,4458.46 4088.78,4458.46 4114.17,4433.07 4114.17,4317.24 4187.85,4243.56 4403.8,4243.56 4443.7,4283.46 C261.2@4528.77,4283.46
  Bottom Layer w7.87: R184.1@4528.77,4228.49 C261.2@4528.77,4282.48
1V8: C119.2 C120.1 C159.1 C160.1 D6.1 R73.1 R165.1 R166.1 R167.1 R185.2 TP10.1 U7.B1 U7.E1 U7.G6 U14.4 U32.4 U33.4 U34.4 | length 25668.2
  Top Layer w7.87: 2844.49,3897.64 v2(3019.69,3897.64) ; v1(10968.5,4358.27) 10996.06,4358.27 11007.87,4370.08 U7.E1@11062.99,4370.08 ; v1(11019.69,4468.5) 11023.62,4464.57 U7.B1@11062.99,4464.57 ; U7.G6@11220.47,4307.09 11240.16,4307.09 v1(11255.91,4291.34)
  Top Layer w39.37: 2332.68,3671.26 v1(2332.68,3771.65) v1(2332.68,3799.21) v1(2332.68,3824.8)
  Top Layer w75: v2(2008.68,1628.45) v2(2008.68,1663.45) v2(2008.68,1698.45) v2(2008.68,1733.45) v2(2008.68,1771.52) 2008.68,2548.05 2228.35,2767.72 2228.35,3618.11 2275.59,3665.35 2622.05,3665.35 2844.49,3887.8 2844.49,3897.64 v1(2844.49,3978.35) v1(2844.49,4005.91) v1(2844.49,4031.5)
  MidLayer4 w49.21: v2(826.77,3311.02) v2(826.77,3283.46) v2(826.77,3255.91) 826.77,3177.17 834.65,3169.29
  MidLayer4 w118.11: 834.65,3169.29 1000,3169.29 1192.91,3362.2 1330.71,3362.2 1393.7,3299.21 2221.79,3299.21 2258,3263 2258,2738.32 1998.68,2479 1998.68,1771.52 1998.68,1733.45 1998.68,1698.45 1998.68,1663.45 v2@1998.68,1658.45
  MidLayer3 w7.87: v2(3019.69,3897.64) 3440.94,3897.64 3582.68,3755.91 4062.99,3755.91 v1(4110.24,3803.15)
  Bottom Layer w7.87: R167.1@811.02,3216.54 788.46,3239.09 788.46,3327.83 803.15,3342.52 830.71,3342.52 854.33,3366.14 901.57,3366.14 937.37,3401.94 U34.4@960.83,3401.94 ; R165.1@2334.65,3712.6 2331.69,3715.55 2299.21,3748.03 2299.21,3917.32 2625.98,4244.09 2771.65,4244.09 2835.01,4307.45 U32.4@2860.43,4307.45 ; R166.1@2838.58,3925.2 2811.02,3952.76 2811.02,4051.18 2846.46,4086.61 3354.33,4086.61 3575.17,4307.45 U33.4@3598.62,4307.45 ; v1(4110.24,3803.15) 4110.24,4028.24 4133.18,4051.18 4500,4051.18 4578.74,4129.92 R185.2@4578.74,4186.13 ; v1(11019.69,4468.5) 11022.64,4465.55 C119.2@11062.99,4465.55
  Bottom Layer w8: R73.1@1993.68,1538.45 1993.79,1538.56 2038.68,1583.45
  Bottom Layer w15: C119.2@11062.99,4465.55 11138.78,4465.55
  Bottom Layer w15.75: v1(10968.5,4358.27) 10992.13,4381.89 11137.8,4381.89 ; 11144.69,4286.42 C120.1@11208.66,4286.42 11250.98,4286.42 v1(11255.91,4291.34)
  Bottom Layer w19.68: TP10.1@10614.94,5281.97 10674.73,5281.97 10700.79,5255.91 10700.79,4703.21 10763,4641 11103.09,4641 11141.73,4602.36 11141.73,4480.32
  Bottom Layer w39.37: R165.1@2332.68,3716.54 v1(2332.68,3771.65) v1(2332.68,3799.21) v1(2332.68,3824.8) ; R166.1@2844.49,3923.23 v1(2844.49,3978.35) v1(2844.49,4005.91) v1(2844.49,4031.5)
  Bottom Layer w49.21: R167.1@826.77,3204.72 v2(826.77,3255.91) v2(826.77,3283.46) v2@826.77,3303.15
  Bottom Layer w50: U14.4@1888.68,1771.52 1970.61,1771.52 ; v2@1995.61,1771.52 1970.61,1771.52 ; v2(2008.68,1733.45) 1989.65,1752.49 1975.18,1766.95 1970.61,1771.52
  Bottom Layer w75: v2(2008.68,1628.45) 2109.35,1527.78 C160.1@2118.68,1518.45 ; v2@2008.68,1631.52 v2(2008.68,1663.45) v2(2008.68,1698.45) v2(2008.68,1733.45) v2@2008.68,1758.45 ; C160.1@2123.97,1517.41 2173.68,1467.7 2173.68,1439.4 2257.66,1355.42 2259.63,1353.45 2259.63,1203.45 2259.63,1118.33 2460.63,917.32 4940,917.32 4940,921 5392,1373 5481,1462 5542,1462 5960.74,1462 ; 5961,1462 5960.74,1462 ; 11141.73,4480.32 11141.73,4185.04 11094.49,4137.8 11094.49,3096.49 11026,3028 11026,2513 11026,2394 10990.27,2358.27 10760,2358.27 9240.16,2358.27 9101.1,2358.27 8538.83,1796 7149.84,1796 7030.85,1677 6175.74,1677 5960.74,1462
1V8D: C262.2 R185.1 U49.9 | length 792.5
  Bottom Layer w5: U49.9@4039.37,4483.46 4089.76,4483.46 4125.98,4447.24 4125.98,4319.57 4191.99,4253.56 4399.66,4253.56 4449.25,4303.15 4558.07,4303.15 C262.2@4578.74,4282.48
  Bottom Layer w7.87: R185.1@4578.74,4228.49 C262.2@4578.74,4282.48
1W_DBID: HDR_T1.92 R18.1 U5.R3 | length 1980.3
  Top Layer w5: HDR_T1.92@7905.51,3531.5 7905.51,3426.62 7933.68,3398.45 8043.68,3398.45 8123.68,3478.45 v5(8233.68,3478.45)
  Top Layer w7.87: v1(9555.12,3366.14) U5.R3@9574.8,3385.83
  MidLayer1 w5: v5(8233.68,3478.45) 8240.01,3472.13 9081.54,3472.13 9171.78,3381.89 9452.76,3381.89 9468.5,3366.14 v1(9555.12,3366.14)
  Bottom Layer w10: v5(8233.68,3478.45) 8288.68,3478.45 8304.86,3462.27 R18.1@8304.86,3433.45
1W_DBPB: EXTHDR1.67 EXTHDR2.67 EXTHDR3.67 HDR_B1.79 R20.2 | length 16332.5
  Top Layer w8: 974.69,2972.44 2007.87,2972.44 ; EXTHDR3.67@3968.5,3409.45 3968.5,3472.28 4032.93,3536.7 4551.93,3536.7 v2(4583.68,3568.45)
  Top Layer w10: 952.76,2994.38 974.69,2972.44 ; 953.68,2993.45 EXTHDR1.67@953.68,3085.69 ; 2007.87,2972.44 2031.5,2948.82 2031.5,2700.79 1913.39,2582.68 1913.39,1602.36 1972.44,1543.31 2047.24,1543.31 2074.8,1570.87 2074.8,2492.13 2291.34,2708.66 2291.34,2944.88 2314.91,2968.45 2883.68,2968.45 ; EXTHDR2.67@3433.07,3086.61 3433.07,2982.84 3418.68,2968.45 v2(3348.68,2968.45) 2883.68,2968.45 ; HDR_B1.79@7716.54,1318.9 7716.54,1395.6 7698.68,1413.45 6398.68,1413.45 6313.68,1328.45 6313.68,1083.45 5678.68,448.45 5588.68,448.45 5483.68,343.45 5483.68,278.45 5413.68,208.45 4973.68,208.45 4958.68,223.45 4958.68,2058.45 4798.68,2218.45 4798.68,2713.45 4773.68,2738.45 2898.68,2738.45 2883.68,2753.45 2883.68,2968.45
  MidLayer4 w8: v1(4582.68,3456.69) 4582.68,3503.94 4583.68,3504.94 v2(4583.68,3568.45)
  MidLayer3 w10: v2(3348.68,2968.45) 3348.68,3025.85 3425.2,3102.36 4377.95,3102.36 4429.13,3153.54 4429.13,3452.76 4468.5,3492.13 4547.24,3492.13 v1(4582.68,3456.69)
  Bottom Layer w10: v2(3348.68,2968.45) R20.2@3348.68,3057.27
1W_NBID: D12.2 R160.1 R161.1 U5.D2 | length 3583.4
  Top Layer w5: v1(9175.2,4224.4) 9175.2,4128.8 9424,3880 9505,3880 9515,3870 9515,3839.33 U5.D2@9535.43,3818.9
  MidLayer3 w10: v2(6522,4543) 6837.84,4543 7020.84,4360 9147.9,4360 9175.2,4332.7 v1(9175.2,4224.4)
  Bottom Layer w10: D12.2@6477.04,4542 6559.62,4542 ; R160.1@6559.62,4517.47 R161.1@6559.62,4567.47
2V5: C34.1 C35.1 C36.1 C37.1 C38.1 C39.1 C40.1 C41.1 C42.1 C43.1 C44.1 C45.1 C46.1 C47.1 C48.1 C49.1 C50.1 C51.1 C52.1 C53.1 C163.1 C164.1 D7.1 R11.1 R13.1 R14.1 R76.2 R168.1 R169.1 R170.1 R181.2 TP11.1 U5.A2 U5.A9 U5.A18 U5.A25 U5.AE1 U5.AE26 U5.AF2 U5.AF9 U5.AF18 U5.AF25 U5.B1 U5.B26 U5.J1 U5.J26 U5.V1 U5.V26 U15.4 U35.4 U36.4 U37.4 | length 20102.2
  Top Layer w5: v1(9468.5,3267.72) U5.V1@9496.06,3267.72
  Top Layer w7.87: v1(9468.5,3622.05) U5.J1@9496.06,3622.05 ; v1(9476.38,2972.44) U5.AE1@9496.06,2992.13 ; v1(9476.38,3917.32) U5.B1@9496.06,3897.64 ; v1(9515.75,2933.07) U5.AF2@9535.43,2952.76 ; v1(9515.75,3956.7) U5.A2@9535.43,3937.01 ; v1(9811.02,2925.2) U5.AF9@9811.02,2952.76 ; U5.A9@9811.02,3937.01 v14(9811.81,3964.17) ; v1(10165.35,2925.2) U5.AF18@10165.35,2952.76 ; U5.A18@10165.35,3937.01 v1(10165.75,3964.57) ; U5.AF25@10440.95,2952.76 v1(10460.63,2933.07) ; U5.A25@10440.95,3937.01 v1(10460.63,3956.7) ; U5.AE26@10480.32,2992.13 v1(10500,2972.44) ; U5.V26@10480.32,3267.72 v1(10507.87,3267.32) ; U5.J26@10480.32,3622.05 v1(10507.87,3622.05) ; U5.B26@10480.32,3897.64 v1(10500,3917.32)
  MidLayer2 w5: v1(9035.09,3784.68) 9099.59,3784.68 9144.91,3830 9389.05,3830 9398.05,3839 9467,3839 9476.38,3848.38 v1(9476.38,3917.32)
  MidLayer2 w39.37: v1(2234.25,3771.65) v1(2234.25,3799.21) v1(2234.25,3824.8) 2234.25,4236.22 2234.25,4246.06 ; v1(2746.06,3978.35) v1(2746.06,4005.91) v1(2746.06,4031.5) 2746.06,4236.22 2746.06,4246.06 ; 4948.82,4137.8 v2(4948.82,4224.41)
  MidLayer2 w49.21: v2(728.35,3255.91) v2(728.35,3283.46) v2(728.35,3311.02) 728.35,3614.17
  MidLayer2 w137.8: 204.52,3269.48 204.52,2777.61 883.68,2098.45 v2(883.68,1743.45) v2(883.68,1713.45) v2(883.68,1683.45) v2(883.68,1653.45) v2@883.68,1643.45 ; 277.54,3624 913.39,3624 1019.69,3730.3 1019.69,4015.75 1240.16,4236.22 2234.25,4236.22 2746.06,4236.22 4677.17,4236.22 4779.53,4133.86 8578.18,4133.86 8795.66,4351.34 9207.06,4351.34 9333.4,4225 9333.4,4089.2 9412.02,4010.58
  Bottom Layer w5: R11.1@9006.98,3782.17 R11.1@9004.46,3784.68 v1(9035.09,3784.68)
  Bottom Layer w7.87: R170.1@716.54,3212.6 690.04,3239.09 690.04,3319.96 712.6,3342.52 736.22,3342.52 795.64,3401.94 U37.4@813.19,3401.94 ; R168.1@2232.28,3716.54 2200.79,3748.03 2200.79,3877.95 2216.54,3893.7 2228.35,3893.7 2610.24,4275.59 2657.48,4275.59 2689.34,4307.45 U35.4@2712.8,4307.45 ; R169.1@2740.16,3925.2 2712.6,3952.76 2712.6,4051.18 2779.53,4118.11 3236.22,4118.11 3425.56,4307.45 U36.4@3450.98,4307.45
  Bottom Layer w8: R76.2@869.86,1523.45 R76.2@874.84,1523.45 903.68,1523.45
  Bottom Layer w10: v2(4948.82,4224.41) 5003.94,4224.41 5035.43,4255.91 5035.43,4377.01 5023.15,4389.29 R181.2@4998.03,4389.29
  Bottom Layer w12: C35.1@9371.02,2922.46 9418.56,2970 v1@9466,2970 ; C37.1@9465.68,4061.97 9515.75,4011.9 v1(9515.75,3956.7) ; C40.1@9468.5,3236.22 9468.5,3237.2 v1(9468.5,3267.72) ; v1(9468.5,3622.05) 9468.5,3653.27 C44.1@9468.5,3653.54 ; C47.1@9476.38,3003.35 v1(9476.38,2972.44) v1(9515.75,2933.07) C50.1@9547.24,2933.07 ; C53.1@9476.38,3885.83 v1(9476.38,3917.32) v1(9515.75,3956.7) ; C45.1@9546.65,3956.7 v1(9515.75,3956.7) ; C52.1@9779.53,2925.2 9779.8,2925.2 v1(9811.02,2925.2) ; C41.1@9784.13,3963.98 v1(9784.13,3993.02) ; v1(10165.35,2925.2) 10196.18,2925.2 C42.1@10196.85,2925.2 ; C38.1@10196.18,3965.16 v1(10196.18,3994.2) ; C46.1@10429.13,3956.69 v1(10460.63,3956.7) ; C43.1@10429.73,2933.07 v1(10460.63,2933.07) v1(10500,2972.44) ; C48.1@10500,3003.94 v1(10500,2972.44) ; C49.1@10500,3886.42 v1(10500,3917.32) v1(10460.63,3956.7) ; C51.1@10507.88,3236.22 10507.88,3236.5 v1(10507.87,3267.32) ; v1(10507.87,3622.05) 10507.87,3652.87 C39.1@10507.87,3653.54 ; C36.1@10516.27,4056.41 10460.63,4000.76 v1(10460.63,3956.7) ; 10569.25,4300.43 R13.1@10599.28,4300.43 ; 10569.28,4212.6 R14.1@10599.28,4212.6 ; C34.1@10599.79,2916.9 10544.25,2972.44 v1(10500,2972.44)
  Bottom Layer w15.75: C47.1@9476.38,3003.36 C47.1@9476.38,3003.94 ; C45.1@9546.67,3956.7 C45.1@9547.24,3956.7 ; C43.1@10429.14,2933.07 C43.1@10429.71,2933.07 ; C49.1@10500,3885.83 C49.1@10500,3886.4
  Bottom Layer w19.68: TP11.1@10514.94,5281.97 10565,5231.91 10565,4124.77 C36.1@10523.23,4083 ; TP11.1@10514.94,5285.97 TP11.1@10516.94,5283.97
  Bottom Layer w39.37: U15.4@768.68,1771.52 855.61,1771.52 ; R168.1@2234.25,3716.54 v1(2234.25,3771.65) v1(2234.25,3799.21) v1(2234.25,3824.8) ; R169.1@2746.06,3923.23 v1(2746.06,3978.35) v1(2746.06,4005.91) v1(2746.06,4031.5)
  Bottom Layer w49.21: R170.1@728.35,3204.72 v2(728.35,3255.91) v2(728.35,3283.46) v2@728.35,3303.15
  Bottom Layer w50: 855.61,1771.52 v2(883.68,1743.45)
  Bottom Layer w75: 883.68,1728.45 v2(883.68,1713.45) v2(883.68,1683.45) v2(883.68,1653.45) v2(883.68,1623.45) 899.18,1607.95 924.73,1582.41 ; 912.74,1269.2 D7.1@895.57,1252.03 ; 929.68,1566 933.68,1566.02 ; 933.68,1582.41 933.68,1566.02 ; C164.1@1023.97,1566.41 933.68,1566.02 ; D7.1@895.57,1252.03 D7.1@863.68,1220.15 D7.1@895.57,1252.03 ; D7.1@895.57,1252.03 933.68,1290.15 933.68,1413.45 933.68,1566.02
  other v1: 9431,3901 9422,3931 9449.5,3961 9491.1,3981.2 9464.1,3985 9440.7,3993.3
  other v2: 884.68,1593.45
2V5D: C258.2 R181.1 R186.2 U49.10 | length 1407.6
  Bottom Layer w7.87: U49.10@4039.37,4508.46 4113.58,4508.46 4141.73,4480.31 4141.73,4320 4196.73,4265 4394.92,4265 4523.62,4393.7 4547.24,4393.7 4685.04,4255.91 4982.28,4255.91 4997.05,4270.67 C258.2@4997.05,4303.15 R181.1@4997.05,4345.94 ; R186.2@4955.22,4389.29 4955.67,4389.29 R181.1@4998.03,4346.93 R181.1@4998.03,4349.92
